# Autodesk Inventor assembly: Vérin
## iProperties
Shininess: 41.0
Angle Display Precision: 2
Document Length Units: 11269
Document Angle Units: 11279
Document Time Units: 11290
Document Mass Units: 11283
Document Length Units Precision: 3
Document Angle Units Precision: 2
Created: 2002-09
Part Number: Vérin
Document SubType Name: Assemblage
Designer: administrateur
Density: 0.0
Volumn: 0.0
Area: 0.0
PropertySet Name: Model Information
Control State: 0
Master: False
Checked Out: False
Author: administrateur
